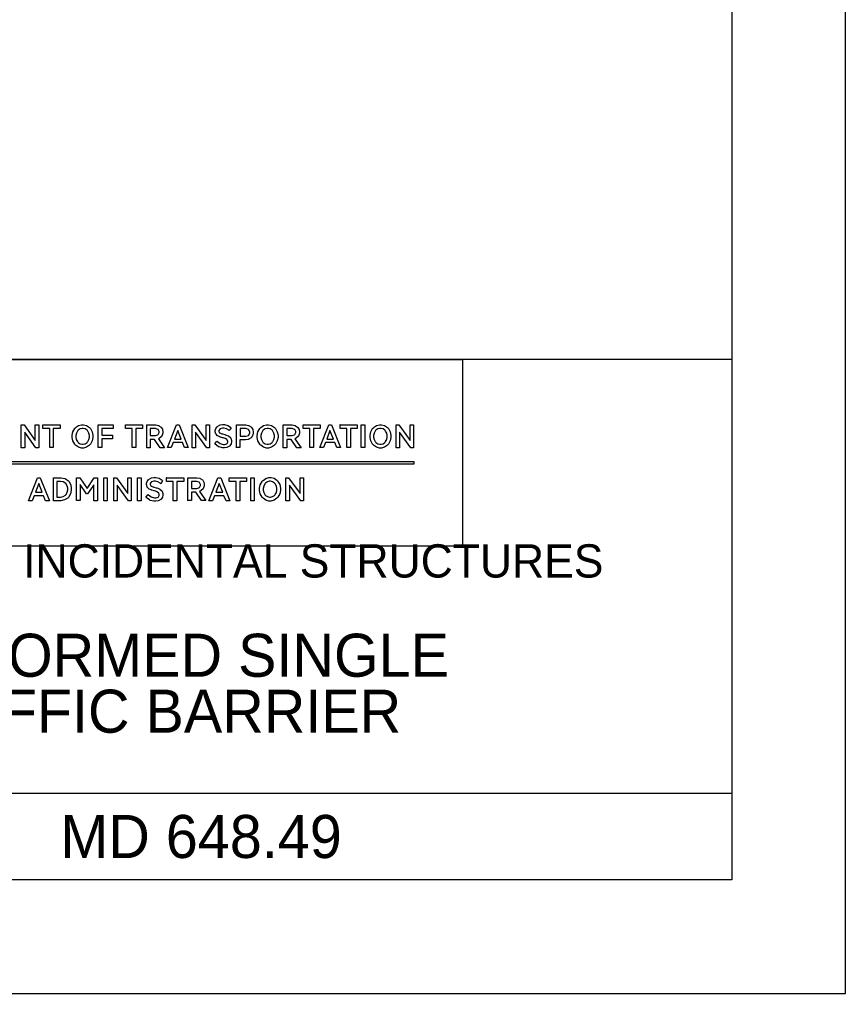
# Model space of a CAD drawing. Extents: x -113.6 to -105.1, y -201.8 to -190.8.
# Drawn here: x -107.419 to -105.115, y -201.778 to -199.062 of the extents above; entities that cross this region are included whole.
import ezdxf

# ---------------------------------------------------------------- set-up
doc = ezdxf.new("R2010")
doc.units = 0
for name, color, linetype in [('BORD-LINE', 7, 'Continuous'), ('Level 13', 7, 'Continuous'), ('MSHA-LOGO', 7, 'Continuous'), ('TTLB-TEXT', 7, 'Continuous'), ('USER-CLIP', 7, 'Continuous'), ('USER-LINE', 7, 'Continuous')]:
    doc.layers.add(name, color=color, linetype=linetype)

msp = doc.modelspace()

# ---------------------------------------------------------------- linework, layer by layer
at = {"layer": 'BORD-LINE'}
for p, q in [((-105.4316, -200.01), (-109.9045, -200.01)), ((-109.9045, -201.219), (-105.4316, -201.219))]:
    msp.add_line(p, q, dxfattribs=at)
msp.add_lwpolyline([(-112.8058, -191.1077), (-105.4316, -191.1077), (-105.4316, -201.4608), (-112.8058, -201.4608)], close=True, dxfattribs=at)
at = {"layer": 'MSHA-LOGO'}
for points in [[(-107.2632, -200.2013), (-107.2619, -200.1997), (-107.2539, -200.1942), (-107.2455, -200.1918), (-107.2426, -200.1918), (-107.2398, -200.1918), (-107.2313, -200.194), (-107.2234, -200.1994), (-107.222, -200.201), (-107.2206, -200.2025), (-107.2157, -200.2114), (-107.2135, -200.2211), (-107.2135, -200.2243), (-107.2135, -200.2275), (-107.2157, -200.2371), (-107.2206, -200.2461), (-107.222, -200.2477), (-107.2234, -200.2492), (-107.2313, -200.2546), (-107.2398, -200.2569), (-107.2426, -200.2569), (-107.2455, -200.2569), (-107.2539, -200.2546), (-107.2619, -200.2492), (-107.2632, -200.2477), (-107.2646, -200.2461), (-107.2696, -200.2372), (-107.2717, -200.2275), (-107.2717, -200.2243), (-107.2717, -200.2211), (-107.2696, -200.2117), (-107.2646, -200.2028)], [(-106.8394, -200.2338), (-106.8398, -200.2335), (-106.8439, -200.2308), (-106.8444, -200.2306), (-106.8448, -200.2304), (-106.8506, -200.2287), (-106.8512, -200.2286), (-106.8519, -200.2284), (-106.8581, -200.2265), (-106.8588, -200.2263), (-106.8594, -200.226), (-106.8652, -200.2233), (-106.8656, -200.223), (-106.8661, -200.2227), (-106.8702, -200.2183), (-106.8705, -200.2177), (-106.8709, -200.2171), (-106.8725, -200.2114), (-106.8725, -200.2095), (-106.8725, -200.2078), (-106.871, -200.2026), (-106.8674, -200.1976), (-106.8663, -200.1967), (-106.8652, -200.1958), (-106.8591, -200.1927), (-106.8525, -200.1914), (-106.8503, -200.1914), (-106.8471, -200.1914), (-106.8377, -200.1937), (-106.8296, -200.1991), (-106.8283, -200.2006), (-106.8336, -200.2085), (-106.8348, -200.2074), (-106.8415, -200.2036), (-106.8483, -200.2019), (-106.8506, -200.2019), (-106.8527, -200.2019), (-106.8585, -200.2036), (-106.8591, -200.2039), (-106.8597, -200.2042), (-106.8624, -200.2082), (-106.8624, -200.2095), (-106.8624, -200.2107), (-106.8602, -200.2141), (-106.8598, -200.2144), (-106.8593, -200.2148), (-106.8539, -200.2172), (-106.8532, -200.2174), (-106.8526, -200.2176), (-106.8454, -200.2195), (-106.8447, -200.2197), (-106.8439, -200.22), (-106.8368, -200.2227), (-106.8362, -200.223), (-106.8355, -200.2233), (-106.83, -200.2279), (-106.8296, -200.2286), (-106.8292, -200.2292), (-106.827, -200.2357), (-106.827, -200.2378), (-106.827, -200.2397), (-106.8285, -200.2453), (-106.8322, -200.2504), (-106.8332, -200.2513), (-106.8343, -200.2522), (-106.8403, -200.2553), (-106.8466, -200.2566), (-106.8486, -200.2566), (-106.8522, -200.2566), (-106.8619, -200.2538), (-106.863, -200.2533), (-106.8642, -200.2527), (-106.8732, -200.2459), (-106.8738, -200.245), (-106.8679, -200.2375), (-106.8666, -200.2389), (-106.859, -200.2443), (-106.8507, -200.2467), (-106.848, -200.2467), (-106.846, -200.2467), (-106.8405, -200.245), (-106.8401, -200.2447), (-106.8396, -200.2444), (-106.8372, -200.2404), (-106.8372, -200.2391), (-106.8372, -200.2385), (-106.8391, -200.2342)], [(-106.7472, -200.2013), (-106.7458, -200.1997), (-106.7378, -200.1942), (-106.7294, -200.1918), (-106.7265, -200.1918), (-106.7237, -200.1918), (-106.7153, -200.194), (-106.7073, -200.1994), (-106.7059, -200.201), (-106.7046, -200.2025), (-106.6996, -200.2114), (-106.6974, -200.2211), (-106.6974, -200.2243), (-106.6974, -200.2275), (-106.6996, -200.2371), (-106.7046, -200.2461), (-106.7059, -200.2477), (-106.7073, -200.2492), (-106.7153, -200.2546), (-106.7237, -200.2569), (-106.7265, -200.2569), (-106.7294, -200.2569), (-106.7378, -200.2546), (-106.7458, -200.2492), (-106.7472, -200.2477), (-106.7486, -200.2461), (-106.7535, -200.2372), (-106.7557, -200.2275), (-106.7557, -200.2243), (-106.7556, -200.222), (-106.7534, -200.2117), (-106.7486, -200.2028)], [(-106.4323, -200.2013), (-106.431, -200.1997), (-106.423, -200.1942), (-106.4146, -200.1918), (-106.4117, -200.1918), (-106.4089, -200.1918), (-106.4005, -200.194), (-106.3925, -200.1994), (-106.3911, -200.201), (-106.3897, -200.2025), (-106.3848, -200.2114), (-106.3826, -200.2211), (-106.3826, -200.2243), (-106.3826, -200.2275), (-106.3848, -200.2371), (-106.3897, -200.2461), (-106.3911, -200.2477), (-106.3925, -200.2492), (-106.4005, -200.2546), (-106.4089, -200.2569), (-106.4117, -200.2569), (-106.4146, -200.2569), (-106.423, -200.2546), (-106.431, -200.2492), (-106.4323, -200.2477), (-106.4337, -200.2461), (-106.4387, -200.2372), (-106.4409, -200.2275), (-106.4409, -200.2243), (-106.4409, -200.2211), (-106.4388, -200.2117), (-106.4338, -200.2028)], [(-107.3725, -200.2562), (-107.4039, -200.2128), (-107.4039, -200.2562), (-107.4134, -200.2562), (-107.4134, -200.1927), (-107.4059, -200.1927), (-107.3745, -200.2362), (-107.3745, -200.1927), (-107.365, -200.1927), (-107.365, -200.2562)], [(-107.3535, -200.1924), (-107.3054, -200.1924), (-107.3054, -200.2026), (-107.3244, -200.2026), (-107.3244, -200.2559), (-107.3342, -200.2559), (-107.3342, -200.2026), (-107.3532, -200.2026), (-107.3532, -200.1924)], [(-107.2557, -200.2401), (-107.2548, -200.2412), (-107.2496, -200.2448), (-107.2441, -200.2464), (-107.2423, -200.2464), (-107.2405, -200.2464), (-107.235, -200.2448), (-107.2298, -200.2412), (-107.2289, -200.2401), (-107.228, -200.2391), (-107.2248, -200.2332), (-107.2233, -200.2265), (-107.2233, -200.2243), (-107.2233, -200.2221), (-107.2248, -200.2154), (-107.228, -200.2095), (-107.2289, -200.2085), (-107.2298, -200.2074), (-107.235, -200.2038), (-107.2405, -200.2023), (-107.2423, -200.2023), (-107.2441, -200.2023), (-107.2496, -200.2038), (-107.2548, -200.2074), (-107.2557, -200.2085), (-107.2566, -200.2095), (-107.2599, -200.2154), (-107.2613, -200.2221), (-107.2613, -200.2243), (-107.2613, -200.2265), (-107.26, -200.2332), (-107.2567, -200.2391)], [(-107.1988, -200.1924), (-107.1569, -200.1924), (-107.1569, -200.2026), (-107.189, -200.2026), (-107.189, -200.2207), (-107.1592, -200.2207), (-107.1592, -200.2309), (-107.189, -200.2309), (-107.189, -200.2559), (-107.1988, -200.2559)], [(-107.1232, -200.1924), (-107.0751, -200.1924), (-107.0751, -200.2026), (-107.0941, -200.2026), (-107.0941, -200.2559), (-107.1039, -200.2559), (-107.1039, -200.2026), (-107.1228, -200.2026), (-107.1228, -200.1924)], [(-107.0636, -200.2562), (-107.0636, -200.1927), (-107.0414, -200.1927), (-107.0386, -200.1927), (-107.0311, -200.1941), (-107.0302, -200.1944), (-107.0295, -200.1946), (-107.0238, -200.1985), (-107.0234, -200.199), (-107.023, -200.1995), (-107.02, -200.2047), (-107.0198, -200.2052), (-107.0195, -200.2058), (-107.0188, -200.211), (-107.0188, -200.2128), (-107.0188, -200.2157), (-107.0215, -200.2235), (-107.0221, -200.2243), (-107.0226, -200.2251), (-107.0302, -200.2309), (-107.0312, -200.2312), (-107.0142, -200.2566), (-107.0263, -200.2566), (-107.0417, -200.2332), (-107.0538, -200.2332), (-107.0538, -200.2566), (-107.0636, -200.2566)], [(-107.0538, -200.2029), (-107.0538, -200.2223), (-107.041, -200.2223), (-107.0388, -200.2223), (-107.0328, -200.2201), (-107.0322, -200.2197), (-107.0317, -200.2193), (-107.0289, -200.2139), (-107.0289, -200.2121), (-107.0289, -200.2104), (-107.0314, -200.2056), (-107.0319, -200.2052), (-107.0324, -200.2048), (-107.0391, -200.2029), (-107.0414, -200.2029)], [(-106.9805, -200.1924), (-106.973, -200.1924), (-106.9481, -200.2559), (-106.9586, -200.2559), (-106.9641, -200.2417), (-106.9897, -200.2417), (-106.9952, -200.2559), (-107.0054, -200.2559)], [(-106.9861, -200.2325), (-106.9674, -200.2325), (-106.9769, -200.2085)], [(-106.8957, -200.2562), (-106.9272, -200.2128), (-106.9272, -200.2562), (-106.9367, -200.2562), (-106.9367, -200.1927), (-106.9291, -200.1927), (-106.8977, -200.2362), (-106.8977, -200.1927), (-106.8882, -200.1927), (-106.8882, -200.2562)], [(-106.8133, -200.2562), (-106.8133, -200.1927), (-106.7904, -200.1927), (-106.7874, -200.1927), (-106.7794, -200.1941), (-106.7786, -200.1944), (-106.7778, -200.1947), (-106.7718, -200.1988), (-106.7714, -200.1993), (-106.771, -200.1998), (-106.7679, -200.2053), (-106.7678, -200.2059), (-106.7676, -200.2065), (-106.7668, -200.2117), (-106.7668, -200.2135), (-106.7668, -200.2153), (-106.7679, -200.2204), (-106.7681, -200.221), (-106.7684, -200.2216), (-106.7716, -200.2271), (-106.772, -200.2276), (-106.7724, -200.2281), (-106.7788, -200.2322), (-106.7796, -200.2325), (-106.7804, -200.2329), (-106.7881, -200.2342), (-106.7907, -200.2342), (-106.8038, -200.2342), (-106.8038, -200.2559), (-106.8133, -200.2559)], [(-106.8031, -200.2029), (-106.8031, -200.2243), (-106.79, -200.2243), (-106.7875, -200.2243), (-106.7797, -200.2216), (-106.7763, -200.2155), (-106.7763, -200.2135), (-106.7763, -200.2115), (-106.7795, -200.2056), (-106.7869, -200.2029), (-106.7894, -200.2029)], [(-106.7396, -200.2401), (-106.7388, -200.2412), (-106.7336, -200.2448), (-106.7281, -200.2464), (-106.7262, -200.2464), (-106.7244, -200.2464), (-106.7189, -200.2448), (-106.7137, -200.2412), (-106.7128, -200.2401), (-106.7119, -200.2391), (-106.7087, -200.2332), (-106.7072, -200.2265), (-106.7072, -200.2243), (-106.7072, -200.2221), (-106.7087, -200.2154), (-106.7119, -200.2095), (-106.7128, -200.2085), (-106.7137, -200.2074), (-106.7189, -200.2038), (-106.7244, -200.2023), (-106.7262, -200.2023), (-106.728, -200.2023), (-106.7334, -200.2038), (-106.7387, -200.2074), (-106.7396, -200.2085), (-106.7405, -200.2095), (-106.7438, -200.2154), (-106.7452, -200.2221), (-106.7452, -200.2243), (-106.7452, -200.2265), (-106.7439, -200.2332), (-106.7406, -200.2391)], [(-106.6827, -200.2562), (-106.6827, -200.1927), (-106.6604, -200.1927), (-106.6577, -200.1927), (-106.6501, -200.1941), (-106.6493, -200.1944), (-106.6486, -200.1946), (-106.6429, -200.1985), (-106.6425, -200.199), (-106.642, -200.1995), (-106.6391, -200.2047), (-106.6389, -200.2052), (-106.6387, -200.2058), (-106.6379, -200.211), (-106.6379, -200.2128), (-106.6379, -200.2157), (-106.6406, -200.2235), (-106.6411, -200.2243), (-106.6417, -200.2251), (-106.6493, -200.2309), (-106.6503, -200.2312), (-106.6333, -200.2566), (-106.6454, -200.2566), (-106.6608, -200.2332), (-106.6729, -200.2332), (-106.6729, -200.2566), (-106.6827, -200.2566)], [(-106.6729, -200.2029), (-106.6729, -200.2223), (-106.6601, -200.2223), (-106.6579, -200.2223), (-106.6519, -200.2201), (-106.6513, -200.2197), (-106.6508, -200.2193), (-106.648, -200.2139), (-106.648, -200.2121), (-106.648, -200.2104), (-106.6505, -200.2056), (-106.651, -200.2052), (-106.6514, -200.2048), (-106.6582, -200.2029), (-106.6604, -200.2029)], [(-106.6277, -200.1924), (-106.5796, -200.1924), (-106.5796, -200.2026), (-106.5986, -200.2026), (-106.5986, -200.2559), (-106.6084, -200.2559), (-106.6084, -200.2026), (-106.6274, -200.2026), (-106.6274, -200.1924)], [(-106.5557, -200.1924), (-106.5482, -200.1924), (-106.5233, -200.2559), (-106.5338, -200.2559), (-106.5394, -200.2417), (-106.5652, -200.2417), (-106.5708, -200.2559), (-106.5806, -200.2559)], [(-106.5616, -200.2325), (-106.543, -200.2325), (-106.5525, -200.2085)], [(-106.5246, -200.1924), (-106.4765, -200.1924), (-106.4765, -200.2026), (-106.4955, -200.2026), (-106.4955, -200.2559), (-106.5053, -200.2559), (-106.5053, -200.2026), (-106.5243, -200.2026), (-106.5243, -200.1924)], [(-106.4651, -200.1924), (-106.4552, -200.1924), (-106.4552, -200.2559), (-106.4651, -200.2559)], [(-106.4252, -200.2401), (-106.4243, -200.2412), (-106.4191, -200.2448), (-106.4136, -200.2464), (-106.4117, -200.2464), (-106.4099, -200.2464), (-106.4044, -200.2448), (-106.3992, -200.2412), (-106.3983, -200.2401), (-106.3974, -200.2391), (-106.3942, -200.2332), (-106.3927, -200.2265), (-106.3927, -200.2243), (-106.3927, -200.2221), (-106.3942, -200.2154), (-106.3974, -200.2095), (-106.3983, -200.2085), (-106.3992, -200.2074), (-106.4044, -200.2038), (-106.4099, -200.2023), (-106.4117, -200.2023), (-106.4135, -200.2023), (-106.4189, -200.2038), (-106.4242, -200.2074), (-106.4252, -200.2085), (-106.4261, -200.2095), (-106.4293, -200.2154), (-106.4307, -200.2221), (-106.4307, -200.2243), (-106.4307, -200.2265), (-106.4293, -200.2332), (-106.4261, -200.2391)], [(-106.3273, -200.2562), (-106.3587, -200.2128), (-106.3587, -200.2562), (-106.3682, -200.2562), (-106.3682, -200.1927), (-106.3607, -200.1927), (-106.3293, -200.2362), (-106.3293, -200.1927), (-106.3198, -200.1927), (-106.3198, -200.2562)], [(-108.4354, -200.2942), (-106.3187, -200.2942), (-106.3187, -200.3021), (-108.4354, -200.3021)], [(-107.3681, -200.3397), (-107.3605, -200.3397), (-107.3352, -200.4039), (-107.3458, -200.4039), (-107.3512, -200.3898), (-107.3774, -200.3898), (-107.3828, -200.4039), (-107.3931, -200.4039)], [(-107.324, -200.3397), (-107.3062, -200.3397), (-107.3024, -200.3397), (-107.2922, -200.3419), (-107.2911, -200.3423), (-107.2901, -200.3427), (-107.2816, -200.3485), (-107.2809, -200.3493), (-107.2803, -200.3501), (-107.2758, -200.3583), (-107.2755, -200.3593), (-107.2752, -200.3603), (-107.2739, -200.3684), (-107.2739, -200.3712), (-107.2739, -200.3745), (-107.276, -200.3844), (-107.2808, -200.3934), (-107.2822, -200.3949), (-107.2836, -200.3965), (-107.2926, -200.4017), (-107.3035, -200.4039), (-107.3071, -200.4039), (-107.324, -200.4039)], [(-107.3141, -200.3503), (-107.3141, -200.3936), (-107.3065, -200.3936), (-107.304, -200.3936), (-107.2966, -200.3922), (-107.2905, -200.3886), (-107.2895, -200.3875), (-107.2886, -200.3865), (-107.2854, -200.3803), (-107.2841, -200.3734), (-107.2841, -200.3712), (-107.2841, -200.3689), (-107.2855, -200.3621), (-107.2896, -200.3556), (-107.2965, -200.3516), (-107.3038, -200.3503), (-107.3062, -200.3503)], [(-107.2592, -200.3397), (-107.2502, -200.3397), (-107.2298, -200.3696), (-107.21, -200.3397), (-107.2013, -200.3397), (-107.2013, -200.4039), (-107.2112, -200.4039), (-107.2112, -200.3593), (-107.2288, -200.3847), (-107.2314, -200.3847), (-107.2493, -200.359), (-107.2493, -200.4036), (-107.2592, -200.4036)], [(-107.1835, -200.3397), (-107.1736, -200.3397), (-107.1736, -200.4039), (-107.1835, -200.4039)], [(-107.1144, -200.4039), (-107.1461, -200.3603), (-107.1461, -200.4039), (-107.1556, -200.4039), (-107.1556, -200.3397), (-107.148, -200.3397), (-107.1164, -200.3837), (-107.1164, -200.3397), (-107.1068, -200.3397), (-107.1068, -200.4039)], [(-107.0892, -200.3397), (-107.0793, -200.3397), (-107.0793, -200.4039), (-107.0892, -200.4039)], [(-107.0304, -200.3818), (-107.0307, -200.3814), (-107.035, -200.3788), (-107.0355, -200.3786), (-107.0361, -200.3784), (-107.0419, -200.3765), (-107.0426, -200.3763), (-107.0432, -200.3761), (-107.0496, -200.3743), (-107.0502, -200.3741), (-107.0509, -200.3738), (-107.0567, -200.3712), (-107.0573, -200.3709), (-107.0578, -200.3705), (-107.062, -200.366), (-107.0624, -200.3654), (-107.0627, -200.3648), (-107.0643, -200.359), (-107.0643, -200.357), (-107.0643, -200.3553), (-107.0626, -200.35), (-107.0589, -200.3451), (-107.0579, -200.3442), (-107.0569, -200.3433), (-107.0507, -200.3403), (-107.0439, -200.3391), (-107.0416, -200.3391), (-107.0384, -200.3391), (-107.0289, -200.3414), (-107.0206, -200.3468), (-107.0192, -200.3484), (-107.0246, -200.3564), (-107.0259, -200.3553), (-107.0326, -200.3513), (-107.0396, -200.3497), (-107.0419, -200.3497), (-107.0441, -200.3497), (-107.05, -200.3513), (-107.0505, -200.3516), (-107.0511, -200.3519), (-107.0541, -200.356), (-107.0541, -200.3574), (-107.0541, -200.3586), (-107.0519, -200.3621), (-107.0515, -200.3625), (-107.0511, -200.3628), (-107.0455, -200.3652), (-107.0448, -200.3654), (-107.0441, -200.3656), (-107.037, -200.3677), (-107.0362, -200.368), (-107.0354, -200.3682), (-107.0282, -200.3709), (-107.0275, -200.3712), (-107.0269, -200.3715), (-107.0213, -200.3763), (-107.0208, -200.377), (-107.0204, -200.3776), (-107.0183, -200.3841), (-107.0183, -200.3863), (-107.0183, -200.3882), (-107.0199, -200.3939), (-107.0236, -200.3992), (-107.0246, -200.4001), (-107.0257, -200.4009), (-107.0318, -200.4041), (-107.0382, -200.4055), (-107.0403, -200.4055), (-107.044, -200.4055), (-107.0538, -200.4029), (-107.055, -200.4023), (-107.0562, -200.4018), (-107.0652, -200.3948), (-107.0659, -200.394), (-107.0598, -200.3863), (-107.0585, -200.3878), (-107.0509, -200.3932), (-107.0423, -200.3956), (-107.0394, -200.3956), (-107.0374, -200.3956), (-107.0319, -200.394), (-107.0314, -200.3936), (-107.0309, -200.3933), (-107.0285, -200.3892), (-107.0285, -200.3879), (-107.0285, -200.3863), (-107.0301, -200.3821)], [(-107.009, -200.3397), (-106.9604, -200.3397), (-106.9604, -200.3503), (-106.9796, -200.3503), (-106.9796, -200.4039), (-106.9895, -200.4039), (-106.9895, -200.3503), (-107.0087, -200.3503), (-107.0087, -200.3397)], [(-106.9489, -200.4039), (-106.9489, -200.3397), (-106.9263, -200.3397), (-106.9235, -200.3397), (-106.9159, -200.3411), (-106.9151, -200.3413), (-106.9143, -200.3416), (-106.9084, -200.3453), (-106.908, -200.3458), (-106.9076, -200.3463), (-106.9047, -200.3517), (-106.9045, -200.3522), (-106.9044, -200.3528), (-106.9036, -200.3579), (-106.9036, -200.3596), (-106.9036, -200.3625), (-106.9065, -200.3704), (-106.9071, -200.3712), (-106.9076, -200.372), (-106.9154, -200.3777), (-106.9164, -200.3779), (-106.8991, -200.4036), (-106.9112, -200.4036), (-106.9269, -200.3802), (-106.939, -200.3802), (-106.939, -200.4036), (-106.9489, -200.4036)], [(-106.939, -200.3503), (-106.939, -200.3699), (-106.9263, -200.3699), (-106.924, -200.3699), (-106.9179, -200.3677), (-106.9173, -200.3673), (-106.9167, -200.3668), (-106.9141, -200.3617), (-106.9141, -200.3599), (-106.9141, -200.3582), (-106.9165, -200.3533), (-106.917, -200.3529), (-106.9175, -200.3525), (-106.9243, -200.3503), (-106.9266, -200.3503)], [(-106.8649, -200.3397), (-106.8572, -200.3397), (-106.832, -200.4039), (-106.8425, -200.4039), (-106.8483, -200.3898), (-106.8745, -200.3898), (-106.8799, -200.4039), (-106.8901, -200.4039)], [(-106.8336, -200.3397), (-106.785, -200.3397), (-106.785, -200.3503), (-106.8042, -200.3503), (-106.8042, -200.4039), (-106.8141, -200.4039), (-106.8141, -200.3503), (-106.8333, -200.3503), (-106.8333, -200.3397)], [(-106.7735, -200.3397), (-106.7636, -200.3397), (-106.7636, -200.4039), (-106.7735, -200.4039)], [(-106.7406, -200.3487), (-106.7392, -200.3471), (-106.7311, -200.3415), (-106.7227, -200.3391), (-106.7199, -200.3391), (-106.717, -200.3391), (-106.7085, -200.3414), (-106.7004, -200.3468), (-106.6991, -200.3484), (-106.6977, -200.3499), (-106.6927, -200.3589), (-106.6904, -200.3686), (-106.6904, -200.3718), (-106.6904, -200.375), (-106.6926, -200.3846), (-106.6977, -200.3936), (-106.6991, -200.3953), (-106.7005, -200.3969), (-106.7086, -200.4023), (-106.7171, -200.4046), (-106.7199, -200.4046), (-106.7227, -200.4046), (-106.7313, -200.4022), (-106.7393, -200.3968), (-106.7406, -200.3953), (-106.7421, -200.3937), (-106.7471, -200.3847), (-106.7492, -200.3751), (-106.7492, -200.3718), (-106.7492, -200.3686), (-106.7471, -200.3592), (-106.7421, -200.3502)], [(-106.7333, -200.3879), (-106.7323, -200.3889), (-106.727, -200.3925), (-106.7216, -200.394), (-106.7199, -200.394), (-106.718, -200.394), (-106.7124, -200.3925), (-106.7071, -200.3889), (-106.7061, -200.3879), (-106.7052, -200.3868), (-106.702, -200.3808), (-106.7007, -200.3741), (-106.7007, -200.3718), (-106.7007, -200.3696), (-106.7021, -200.3629), (-106.7055, -200.3568), (-106.7064, -200.3558), (-106.7074, -200.3547), (-106.7127, -200.3511), (-106.7181, -200.3497), (-106.7199, -200.3497), (-106.7217, -200.3497), (-106.7272, -200.3511), (-106.7324, -200.3547), (-106.7333, -200.3558), (-106.7341, -200.3568), (-106.7373, -200.3628), (-106.7387, -200.3696), (-106.7387, -200.3718), (-106.7387, -200.3741), (-106.7373, -200.3808), (-106.7341, -200.3868)], [(-106.6342, -200.4039), (-106.6659, -200.3603), (-106.6659, -200.4039), (-106.6754, -200.4039), (-106.6754, -200.3397), (-106.6678, -200.3397), (-106.6361, -200.3837), (-106.6361, -200.3397), (-106.6265, -200.3397), (-106.6265, -200.4039)], [(-107.3739, -200.3802), (-107.355, -200.3802), (-107.3646, -200.3558)], [(-106.8707, -200.3802), (-106.8518, -200.3802), (-106.8614, -200.3558)]]:
    msp.add_lwpolyline(points, close=True, dxfattribs=at)
at = {"layer": 'USER-CLIP'}
msp.add_lwpolyline([(-105.1147, -190.7777), (-113.6147, -190.7777), (-113.6147, -201.7777), (-105.1147, -201.7777)], close=True, dxfattribs=at)
at = {"layer": 'USER-LINE'}
msp.add_lwpolyline([(-106.1825, -200.5307), (-109.1536, -200.5307), (-109.1536, -200.01), (-106.1825, -200.01)], close=True, dxfattribs=at)

# ---------------------------------------------------------------- texts
at = {"layer": 'BORD-LINE'}
msp.add_text('HDVBARREIRA', height=6e-12, rotation=180, dxfattribs=at).set_placement((-105.4316, -200.01))
at = {"layer": 'Level 13'}
for s, p in [('DIAGONAL BAR FOR SLIP FORMED SINGLE', (-109.573, -200.8946)), ('FACE CONCRETE TRAFFIC BARRIER', (-109.2067, -201.0506)), ('MD 648.49', (-107.3045, -201.3999))]:
    msp.add_text(s, height=0.12, dxfattribs=at).set_placement(p)
at = {"layer": 'TTLB-TEXT'}
msp.add_text('STANDARDS FOR HIGHWAYS AND INCIDENTAL STRUCTURES', height=0.09269, dxfattribs=at).set_placement((-109.5087, -200.618))

doc.saveas('drawing.dxf')
